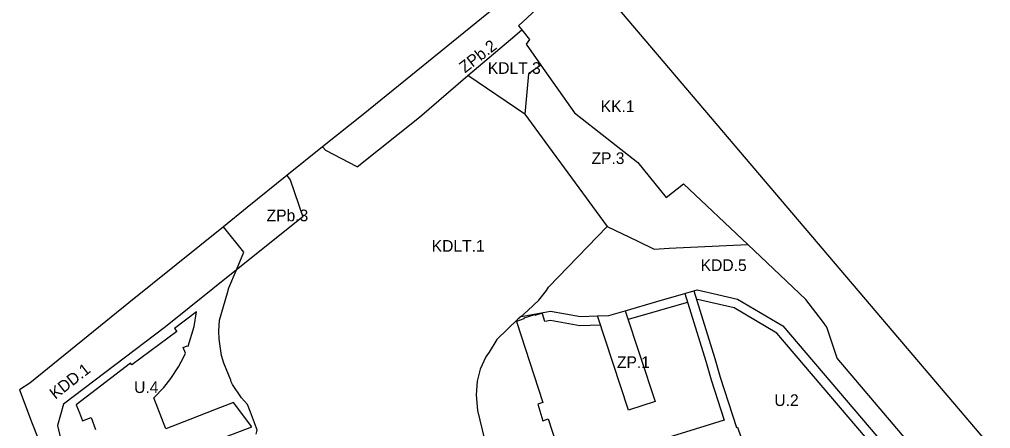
# Model space of a CAD drawing. Extents: x 7424719 to 7426158, y 5545504 to 5546892.
# Drawn here: x 7424952.8 to 7425368.6, y 5546259.1 to 5546434.4 of the extents above; entities that cross this region are included whole.
import ezdxf

# ---------------------------------------------------------------- set-up
doc = ezdxf.new("R2010")
doc.units = 0
for name, color, linetype in [('Linia Zabudowy Nieprzekraczalna', 7, 'Continuous'), ('Linia Zabudowy Obowiązujaca', 7, 'Continuous'), ('Linie Rozgraniczajace', 7, 'Continuous'), ('Oznaczenia Przeznaczenia', 7, 'Continuous')]:
    doc.layers.add(name, color=color, linetype=linetype)

msp = doc.modelspace()

# ---------------------------------------------------------------- linework, layer by layer
at = {"layer": 'Linia Zabudowy Nieprzekraczalna'}
for points in [[(7425238.92, 5546313.12), (7425238.24, 5546312.93), (7425226.88, 5546309.66), (7425213.45, 5546305.78)], [(7425334.12, 5546231.87), (7425330.7, 5546236.97), (7425277.09, 5546300.01), (7425258.76, 5546310.8), (7425243.13, 5546314.34), (7425242.76, 5546314.24)], [(7425201.59, 5546303.44), (7425192.75, 5546303.14), (7425180.17, 5546305.38), (7425177.8, 5546304.93)]]:
    msp.add_lwpolyline(points, dxfattribs=at)
at = {"layer": 'Linia Zabudowy Obowiązujaca'}
for points in [[(7425041.44, 5546255.66), (7425052.33, 5546259.88), (7425044.5, 5546270.32), (7425037.06, 5546267.45), (7425025.8, 5546263.03), (7425015.5, 5546258.94), (7425010.39, 5546272.32), (7425014.6, 5546276.72), (7425017.65, 5546280.48), (7425020.94, 5546285.56), (7425023.19, 5546289.85), (7425023.92, 5546291.47), (7425022.95, 5546293.88), (7425024.69, 5546294.51), (7425025.13, 5546294.37), (7425027.65, 5546302.77), (7425028.68, 5546309.06), (7425019.17, 5546301.91), (7425020.15, 5546300.64), (7425000.94, 5546286.35), (7425000.42, 5546287.05), (7424977.08, 5546269.3), (7424978.6, 5546265.78), (7424979.87, 5546262.4), (7424983.53, 5546263.81), (7424985.43, 5546258.75)], [(7425177.8, 5546304.93), (7425176.73, 5546308.26), (7425176.61, 5546308.52), (7425173.45, 5546307.58), (7425173.34, 5546307.88), (7425168.78, 5546306.42), (7425168.81, 5546306.09), (7425165.69, 5546304.97), (7425176.94, 5546270.19), (7425174.7, 5546269.52), (7425176.86, 5546262.47), (7425179.19, 5546263.22), (7425190.44, 5546228.41), (7425193.63, 5546229.37), (7425193.77, 5546229.04), (7425198.26, 5546230.53), (7425198.17, 5546230.85), (7425201.36, 5546232.03)]]:
    msp.add_lwpolyline(points, dxfattribs=at)
at = {"layer": 'Linie Rozgraniczajace'}
for p, q in [((7425978.47, 5545533.55), (7425205.67, 5546443.4)), ((7425169.24, 5546393.8), (7425144.87, 5546410.35))]:
    msp.add_line(p, q, dxfattribs=at)
for points in [[(7425171.34, 5546452.02), (7425155.91, 5546439.18), (7425100.05, 5546393.63), (7425082.63, 5546379.87), (7425067.33, 5546367.48), (7425050.39, 5546353.84), (7425040.18, 5546345.6)], [(7425171.34, 5546452.02), (7425176.92, 5546445.38), (7425172.18, 5546441.45), (7425174.26, 5546438.77), (7425166.51, 5546431.64), (7425167.85, 5546429.93), (7425171.13, 5546425.76), (7425169.76, 5546423.76), (7425176.08, 5546414.76), (7425190.41, 5546394.33), (7425204.26, 5546383.55)], [(7425097.36, 5546371.23), (7425124.12, 5546392.61), (7425144.87, 5546410.35), (7425163.01, 5546425.86), (7425167.85, 5546429.93)], [(7425176.08, 5546414.76), (7425170.76, 5546411.08), (7425169.24, 5546393.8), (7425179.31, 5546380.02), (7425187.6, 5546368.68), (7425204.38, 5546345.68), (7425217.24, 5546339.55), (7425224.62, 5546336.02), (7425230.93, 5546336.34), (7425264.61, 5546337.96)], [(7425204.26, 5546383.55), (7425217.61, 5546373.17), (7425229.69, 5546358.15), (7425237.08, 5546363.97)], [(7425097.36, 5546371.23), (7425083.99, 5546378.19), (7425082.63, 5546379.87)], [(7425067.33, 5546367.48), (7425068.8, 5546365.73), (7425074.1, 5546349.89), (7425045.73, 5546327.08), (7425015.41, 5546302.7), (7424971.75, 5546269.52), (7424969.15, 5546260.38), (7424970.61, 5546254.21), (7424972.18, 5546248.99), (7424974.87, 5546240.61), (7424979.68, 5546227.83)], [(7425296.58, 5546305.15), (7425289.49, 5546314.47), (7425264.61, 5546337.96), (7425237.08, 5546363.97)], [(7425040.18, 5546345.6), (7424999.67, 5546312.93), (7424957.24, 5546278.61)], [(7425045.73, 5546327.08), (7425048.94, 5546334.74), (7425040.18, 5546345.6)], [(7425167.7, 5546307.07), (7425170.42, 5546309.66), (7425175.18, 5546314.11), (7425178.44, 5546318.21), (7425179.34, 5546319.65), (7425204.38, 5546345.68)], [(7425054.2, 5546256.63), (7425054.62, 5546258.34), (7425054.38, 5546259.25), (7425051.78, 5546266.05), (7425050.52, 5546269.41), (7425047.85, 5546272.19), (7425044.11, 5546277.95), (7425043.52, 5546279.07), (7425043.29, 5546279.76), (7425040.34, 5546287.08), (7425039.35, 5546290.33), (7425038.28, 5546297.38), (7425038.16, 5546300.88), (7425038.51, 5546305.58), (7425041.88, 5546317.19), (7425042.53, 5546319.43), (7425045.73, 5546327.08)], [(7425167.7, 5546307.07), (7425180.14, 5546309.45), (7425193.04, 5546307.15), (7425200.3, 5546307.4), (7425205.21, 5546307.57), (7425212.21, 5546309.59), (7425225.77, 5546313.5), (7425237.13, 5546316.77), (7425237.74, 5546316.95), (7425238.1, 5546317.05), (7425241.58, 5546318.06), (7425250.48, 5546289.16), (7425252.76, 5546281.08), (7425259.75, 5546259.53), (7425260.27, 5546259.68), (7425266.02, 5546243.08)], [(7425237.74, 5546316.95), (7425246.64, 5546288.03), (7425248.93, 5546279.92), (7425254.53, 5546262.65)], [(7425241.58, 5546318.06), (7425243.02, 5546318.47), (7425251.63, 5546316.51), (7425260.25, 5546314.56), (7425279.7, 5546303.12), (7425306.8, 5546271.25), (7425333.9, 5546239.39), (7425341.81, 5546227.58)], [(7425212.21, 5546309.59), (7425224.95, 5546270.63), (7425213.54, 5546266.9), (7425200.3, 5546307.4)], [(7425167.7, 5546307.07), (7425166.3, 5546306.1), (7425157.27, 5546297.21), (7425153.88, 5546291.79), (7425152.5, 5546289.77), (7425150.14, 5546284.54), (7425148.8, 5546279.34), (7425148.35, 5546273.48), (7425148.92, 5546266.87), (7425153.77, 5546246.63), (7425157.7, 5546230.44), (7425159.39, 5546225.48)], [(7425354.92, 5546228.03), (7425302.89, 5546289.28), (7425298.52, 5546302.6), (7425296.58, 5546305.15)], [(7424957.24, 5546278.61), (7424952.83, 5546275.68), (7424958.33, 5546261.26), (7424972.58, 5546225.13), (7424998.07, 5546160.52), (7424989.29, 5546158.65), (7424968.14, 5546152.12), (7424974.15, 5545966.53), (7424974.59, 5545952.99), (7425152.89, 5545960.96), (7425151.54, 5545949.85), (7425136.55, 5545826.39)], [(7425254.53, 5546262.65), (7425238.04, 5546257.6), (7425231.04, 5546255.45)]]:
    msp.add_lwpolyline(points, dxfattribs=at)

# ---------------------------------------------------------------- texts
at = {"layer": 'Oznaczenia Przeznaczenia'}
for s, rotation, p in [('ZPb.2', 37.7563, (7425143.54, 5546411.24)), ('KDD.1', 38.1178, (7424968.2, 5546271.39))]:
    msp.add_text(s, height=5, rotation=rotation, dxfattribs=at).set_placement(p)
for s, p in [('KDLT.3', (7425153.34, 5546411.09)), ('KK.1', (7425201.68, 5546394.69)), ('ZP.3', (7425197.74, 5546372.46)), ('ZPb.3', (7425058.65, 5546347.93)), ('KDLT.1', (7425129.33, 5546334.86)), ('KDD.5', (7425244.48, 5546326.62)), ('ZP.1', (7425208.63, 5546285.05)), ('U.4', (7425001.94, 5546274.32)), ('U.2', (7425276.03, 5546268.75))]:
    msp.add_text(s, height=5, dxfattribs=at).set_placement(p)

doc.saveas('drawing.dxf')
